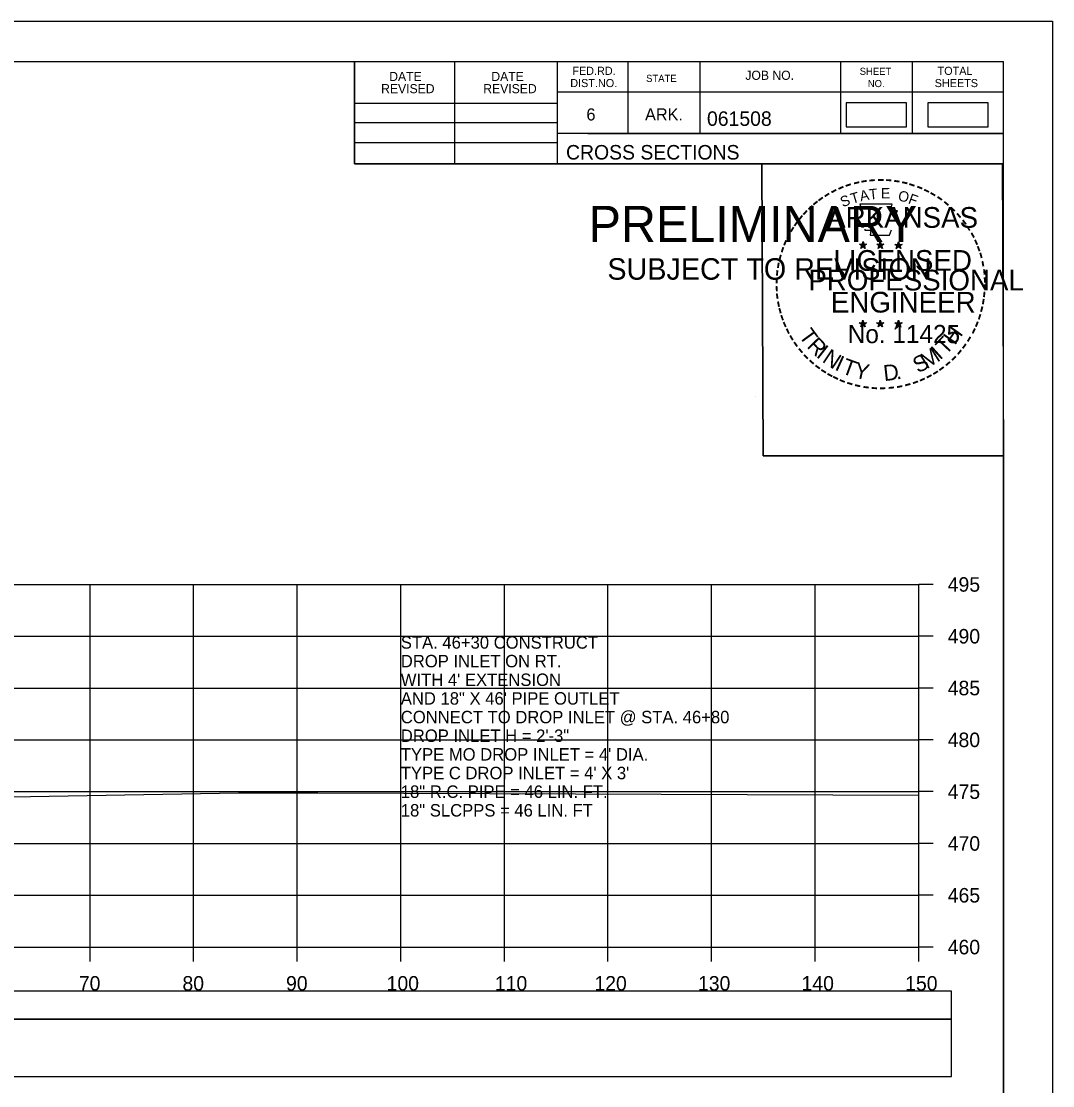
# Model space of a CAD drawing. Extents: x 1371057 to 1372761, y 380005 to 390517.
# Drawn here: x 1371624.2 to 1371723.8, y 382462.4 to 382565.1 of the extents above; entities that cross this region are included whole.
import ezdxf

# ---------------------------------------------------------------- set-up
doc = ezdxf.new("R2010")
doc.units = 0
for name, color, linetype in [('R_Axis', 7, 'Continuous'), ('R_Axis Annot', 7, 'Continuous'), ('R_Border', 7, 'Continuous'), ('R_Border PE', 7, 'Continuous'), ('R_Border Prem', 7, 'Continuous'), ('R_Detour', 7, 'Continuous'), ('R_Dimension', 7, 'Continuous'), ('R_Exist Surface', 7, 'Continuous'), ('R_Grid', 7, 'Continuous'), ('R_No Plot', 7, 'Continuous'), ('R_Water Annot', 7, 'Continuous')]:
    doc.layers.add(name, color=color, linetype=linetype)

msp = doc.modelspace()

# ---------------------------------------------------------------- linework, layer by layer
at = {"layer": 'R_Axis'}
for p, q in [((1371710.87, 382475.78), (1371710.87, 382510.78)), ((1371712.27, 382510.78), (1371710.87, 382510.78)), ((1371712.27, 382505.78), (1371710.87, 382505.78)), ((1371712.27, 382500.78), (1371710.87, 382500.78)), ((1371712.27, 382495.78), (1371710.87, 382495.78)), ((1371712.27, 382490.78), (1371710.87, 382490.78)), ((1371712.27, 382485.78), (1371710.87, 382485.78)), ((1371712.27, 382480.78), (1371710.87, 382480.78)), ((1371410.87, 382475.78), (1371710.87, 382475.78)), ((1371630.87, 382474.38), (1371630.87, 382475.78)), ((1371640.87, 382474.38), (1371640.87, 382475.78)), ((1371650.87, 382474.38), (1371650.87, 382475.78)), ((1371660.87, 382474.38), (1371660.87, 382475.78)), ((1371670.87, 382474.38), (1371670.87, 382475.78)), ((1371680.87, 382474.38), (1371680.87, 382475.78)), ((1371690.87, 382474.38), (1371690.87, 382475.78)), ((1371700.87, 382474.38), (1371700.87, 382475.78)), ((1371710.87, 382474.38), (1371710.87, 382475.78)), ((1371712.27, 382475.78), (1371710.87, 382475.78))]:
    msp.add_line(p, q, dxfattribs=at)
at = {"layer": 'R_Border'}
for p, q in [((1371402.87, 382561.24), (1371719.05, 382561.24)), ((1371656.41, 382551.36), (1371656.41, 382561.24)), ((1371666.09, 382551.36), (1371666.09, 382561.24)), ((1371675.95, 382561.24), (1371675.95, 382551.36)), ((1371682.79, 382561.24), (1371682.79, 382554.3)), ((1371689.73, 382561.24), (1371689.73, 382554.3)), ((1371703.31, 382561.24), (1371703.31, 382554.3)), ((1371710.25, 382561.24), (1371710.25, 382554.3)), ((1371719.05, 382355.78), (1371719.05, 382561.24)), ((1371719.05, 382558.3), (1371675.95, 382558.3)), ((1371719.05, 382558.32), (1371719.05, 382558.32)), ((1371656.41, 382557.22), (1371675.95, 382557.22)), ((1371656.41, 382555.36), (1371675.95, 382555.36)), ((1371719.05, 382554.3), (1371675.95, 382554.3)), ((1371678.91, 382554.3), (1371719.05, 382554.3)), ((1371656.41, 382553.42), (1371675.95, 382553.42)), ((1371719.05, 382551.36), (1371656.41, 382551.36))]:
    msp.add_line(p, q, dxfattribs=at)
at = {"layer": 'R_Border PE'}
for p, q in [((1371705.14, 382543.61), (1371705.49, 382543.5)), ((1371705.14, 382543.61), (1371705.39, 382543.57)), ((1371705.14, 382543.61), (1371705.37, 382543.49)), ((1371705.27, 382543.2), (1371705.49, 382543.5)), ((1371705.27, 382543.2), (1371705.4, 382543.45)), ((1371705.27, 382543.2), (1371705.48, 382543.42)), ((1371705.49, 382543.87), (1371705.45, 382543.61)), ((1371705.7, 382543.2), (1371705.48, 382543.42)), ((1371705.49, 382543.5), (1371705.49, 382543.87)), ((1371705.49, 382543.87), (1371705.54, 382543.62)), ((1371705.83, 382543.61), (1371705.49, 382543.5)), ((1371705.7, 382543.2), (1371705.49, 382543.5)), ((1371705.83, 382543.61), (1371705.55, 382543.56)), ((1371705.7, 382543.2), (1371705.56, 382543.5)), ((1371705.83, 382543.61), (1371705.63, 382543.51)), ((1371706.81, 382543.61), (1371707.16, 382543.5)), ((1371706.81, 382543.61), (1371707.06, 382543.57)), ((1371706.81, 382543.61), (1371707.04, 382543.49)), ((1371706.94, 382543.2), (1371707.16, 382543.5)), ((1371706.94, 382543.2), (1371707.07, 382543.45)), ((1371706.94, 382543.2), (1371707.15, 382543.42)), ((1371707.16, 382543.87), (1371707.12, 382543.61)), ((1371707.37, 382543.2), (1371707.15, 382543.42)), ((1371707.16, 382543.5), (1371707.16, 382543.87)), ((1371707.16, 382543.87), (1371707.21, 382543.62)), ((1371707.5, 382543.61), (1371707.16, 382543.5)), ((1371707.37, 382543.2), (1371707.16, 382543.5)), ((1371707.5, 382543.61), (1371707.22, 382543.56)), ((1371707.37, 382543.2), (1371707.23, 382543.5)), ((1371707.5, 382543.61), (1371707.3, 382543.51)), ((1371708.57, 382543.6), (1371708.92, 382543.49)), ((1371708.57, 382543.6), (1371708.82, 382543.56)), ((1371708.57, 382543.6), (1371708.81, 382543.48)), ((1371708.7, 382543.19), (1371708.92, 382543.49)), ((1371708.7, 382543.19), (1371708.83, 382543.44)), ((1371708.7, 382543.19), (1371708.92, 382543.41)), ((1371708.92, 382543.85), (1371708.88, 382543.6)), ((1371708.92, 382543.49), (1371708.92, 382543.85)), ((1371708.92, 382543.85), (1371708.97, 382543.6)), ((1371709.27, 382543.6), (1371708.92, 382543.49)), ((1371709.13, 382543.19), (1371708.92, 382543.49)), ((1371709.13, 382543.19), (1371708.92, 382543.41)), ((1371709.27, 382543.6), (1371708.98, 382543.55)), ((1371709.13, 382543.19), (1371709, 382543.48)), ((1371709.27, 382543.6), (1371709.06, 382543.5)), ((1371705.48, 382536.29), (1371705.44, 382536.04)), ((1371705.48, 382535.93), (1371705.48, 382536.29)), ((1371705.48, 382536.29), (1371705.53, 382536.04)), ((1371707.15, 382536.29), (1371707.11, 382536.04)), ((1371707.15, 382535.93), (1371707.15, 382536.29)), ((1371707.15, 382536.29), (1371707.2, 382536.04)), ((1371708.92, 382536.28), (1371708.88, 382536.03)), ((1371708.92, 382535.92), (1371708.92, 382536.28)), ((1371708.92, 382536.28), (1371708.97, 382536.03)), ((1371705.13, 382536.04), (1371705.48, 382535.93)), ((1371705.13, 382536.04), (1371705.39, 382535.99)), ((1371705.13, 382536.04), (1371705.37, 382535.92)), ((1371705.27, 382535.63), (1371705.48, 382535.93)), ((1371705.27, 382535.63), (1371705.39, 382535.88)), ((1371705.27, 382535.63), (1371705.48, 382535.85)), ((1371705.83, 382536.04), (1371705.48, 382535.93)), ((1371705.7, 382535.63), (1371705.48, 382535.93)), ((1371705.7, 382535.63), (1371705.48, 382535.85)), ((1371705.83, 382536.04), (1371705.54, 382535.99)), ((1371705.7, 382535.63), (1371705.56, 382535.92)), ((1371705.83, 382536.04), (1371705.63, 382535.94)), ((1371706.8, 382536.04), (1371707.15, 382535.93)), ((1371706.8, 382536.04), (1371707.06, 382535.99)), ((1371706.8, 382536.04), (1371707.04, 382535.92)), ((1371706.94, 382535.63), (1371707.15, 382535.93)), ((1371706.94, 382535.63), (1371707.06, 382535.88)), ((1371706.94, 382535.63), (1371707.15, 382535.85)), ((1371707.5, 382536.04), (1371707.15, 382535.93)), ((1371707.36, 382535.63), (1371707.15, 382535.93)), ((1371707.36, 382535.63), (1371707.15, 382535.85)), ((1371707.5, 382536.04), (1371707.21, 382535.99)), ((1371707.36, 382535.63), (1371707.23, 382535.92)), ((1371707.5, 382536.04), (1371707.29, 382535.94)), ((1371708.57, 382536.03), (1371708.92, 382535.92)), ((1371708.57, 382536.03), (1371708.82, 382535.98)), ((1371708.57, 382536.03), (1371708.81, 382535.91)), ((1371708.7, 382535.62), (1371708.92, 382535.92)), ((1371708.7, 382535.62), (1371708.83, 382535.87)), ((1371708.7, 382535.62), (1371708.92, 382535.84)), ((1371709.27, 382536.03), (1371708.92, 382535.92)), ((1371709.13, 382535.62), (1371708.92, 382535.92)), ((1371709.13, 382535.62), (1371708.92, 382535.84)), ((1371709.27, 382536.03), (1371708.98, 382535.98)), ((1371709.13, 382535.62), (1371708.99, 382535.91)), ((1371709.27, 382536.03), (1371709.06, 382535.93))]:
    msp.add_line(p, q, dxfattribs=at)
for points in [[(1371705.18, 382547.49), (1371705.45, 382546.66)], [(1371708.69, 382546.57), (1371708.83, 382546.85), (1371708.15, 382546.83), (1371708.29, 382547.49), (1371705.18, 382547.49)], [(1371705.67, 382545.07), (1371705.67, 382544.98), (1371706.23, 382544.96), (1371706.18, 382544.49), (1371708.05, 382544.49), (1371708.25, 382545.02)], [(1371705.49, 382543.87), (1371705.7, 382543.2), (1371705.14, 382543.61), (1371705.83, 382543.61), (1371705.27, 382543.2), (1371705.49, 382543.87)], [(1371707.16, 382543.87), (1371707.37, 382543.2), (1371706.81, 382543.61), (1371707.5, 382543.61), (1371706.94, 382543.2), (1371707.16, 382543.87)], [(1371708.92, 382543.85), (1371709.13, 382543.19), (1371708.57, 382543.6), (1371709.27, 382543.6), (1371708.7, 382543.19), (1371708.92, 382543.85)], [(1371705.48, 382536.29), (1371705.7, 382535.63), (1371705.13, 382536.04), (1371705.83, 382536.04), (1371705.27, 382535.63), (1371705.48, 382536.29)], [(1371707.15, 382536.29), (1371707.36, 382535.63), (1371706.8, 382536.04), (1371707.5, 382536.04), (1371706.94, 382535.63), (1371707.15, 382536.29)], [(1371708.92, 382536.28), (1371709.13, 382535.62), (1371708.57, 382536.03), (1371709.27, 382536.03), (1371708.7, 382535.62), (1371708.92, 382536.28)]]:
    msp.add_lwpolyline(points, dxfattribs=at)
for centre, radius in [((1371705.49, 382543.5), 0.172), ((1371705.49, 382543.5), 0.145), ((1371705.49, 382543.5), 0.116), ((1371705.49, 382543.5), 0.0991), ((1371705.49, 382543.5), 0.0747), ((1371705.49, 382543.5), 0.0495), ((1371705.49, 382543.5), 0.0296), ((1371707.16, 382543.5), 0.172), ((1371707.16, 382543.5), 0.145), ((1371707.16, 382543.5), 0.116), ((1371707.16, 382543.5), 0.0991), ((1371707.16, 382543.5), 0.0747), ((1371707.16, 382543.5), 0.0495), ((1371707.16, 382543.5), 0.0296), ((1371708.92, 382543.49), 0.172), ((1371708.92, 382543.49), 0.145), ((1371708.92, 382543.49), 0.116), ((1371708.92, 382543.49), 0.0991), ((1371708.92, 382543.49), 0.0747), ((1371708.92, 382543.49), 0.0495), ((1371708.92, 382543.49), 0.0296), ((1371705.48, 382535.93), 0.172), ((1371705.48, 382535.93), 0.145), ((1371705.48, 382535.93), 0.116), ((1371705.48, 382535.93), 0.0991), ((1371705.48, 382535.93), 0.0747), ((1371705.48, 382535.93), 0.0495), ((1371705.48, 382535.93), 0.0296), ((1371707.15, 382535.93), 0.172), ((1371707.15, 382535.93), 0.145), ((1371707.15, 382535.93), 0.116), ((1371707.15, 382535.93), 0.0991), ((1371707.15, 382535.93), 0.0747), ((1371707.15, 382535.93), 0.0495), ((1371707.15, 382535.93), 0.0296), ((1371708.92, 382535.92), 0.172), ((1371708.92, 382535.92), 0.145), ((1371708.92, 382535.92), 0.116), ((1371708.92, 382535.92), 0.0991), ((1371708.92, 382535.92), 0.0747), ((1371708.92, 382535.92), 0.0495), ((1371708.92, 382535.92), 0.0296)]:
    msp.add_circle(centre, radius, dxfattribs=at)
at = {"layer": 'R_Detour'}
msp.add_lwpolyline([(1371407.72, 382468.82), (1371714.03, 382468.82), (1371714.03, 382471.53), (1371407.72, 382471.53)], close=True, dxfattribs=at)
at = {"layer": 'R_Dimension'}
for points in [[(1371703.87, 382554.95), (1371709.7, 382554.95), (1371709.7, 382557.26), (1371703.87, 382557.26)], [(1371711.74, 382554.95), (1371717.57, 382554.95), (1371717.57, 382557.26), (1371711.74, 382557.26)], [(1371407.72, 382463.3), (1371714.03, 382463.3), (1371714.03, 382468.82), (1371407.72, 382468.82)]]:
    msp.add_lwpolyline(points, close=True, dxfattribs=at)
at = {"layer": 'R_Exist Surface'}
msp.add_lwpolyline([(1371621.42, 382490.24), (1371645.2, 382490.68), (1371646.29, 382490.68), (1371652.85, 382490.66), (1371710.87, 382490.44)], dxfattribs=at)
at = {"layer": 'R_Grid'}
for p, q in [((1371410.87, 382510.78), (1371710.87, 382510.78)), ((1371630.87, 382475.78), (1371630.87, 382510.78)), ((1371640.87, 382475.78), (1371640.87, 382510.78)), ((1371650.87, 382475.78), (1371650.87, 382510.78)), ((1371660.87, 382475.78), (1371660.87, 382510.78)), ((1371670.87, 382475.78), (1371670.87, 382510.78)), ((1371680.87, 382475.78), (1371680.87, 382510.78)), ((1371690.87, 382475.78), (1371690.87, 382510.78)), ((1371700.87, 382475.78), (1371700.87, 382510.78)), ((1371710.87, 382475.78), (1371710.87, 382510.78)), ((1371410.87, 382505.78), (1371710.87, 382505.78)), ((1371410.87, 382500.78), (1371710.87, 382500.78)), ((1371410.87, 382495.78), (1371710.87, 382495.78)), ((1371410.87, 382490.78), (1371710.87, 382490.78)), ((1371410.87, 382485.78), (1371710.87, 382485.78)), ((1371410.87, 382480.78), (1371710.87, 382480.78)), ((1371410.87, 382475.78), (1371710.87, 382475.78))]:
    msp.add_line(p, q, dxfattribs=at)
at = {"layer": 'R_No Plot'}
for p, q in [((1371390.47, 382565.13), (1371723.8, 382565.13)), ((1371695.09, 382528.9), (1371695.09, 382528.9))]:
    msp.add_line(p, q, dxfattribs=at)
for points in [[(1371390.46, 382565.13), (1371723.8, 382565.13), (1371723.8, 382351.79), (1371390.46, 382351.79)], [(1371636.79, 382561.24), (1371656.41, 382561.24), (1371656.41, 382551.36), (1371672.52, 382551.36), (1371695.72, 382551.36), (1371695.84, 382523.2), (1371719.05, 382523.2), (1371719.05, 382355.78), (1371402.87, 382355.78), (1371402.87, 382561.24)], [(1371695.72, 382551.36), (1371718.93, 382551.36), (1371719.05, 382523.2), (1371695.84, 382523.2)]]:
    msp.add_lwpolyline(points, close=True, dxfattribs=at)

# ---------------------------------------------------------------- texts
at = {"layer": 'R_Axis Annot'}
for s, p in [('495', (1371713.67, 382510.08)), ('490', (1371713.67, 382505.08)), ('485', (1371713.67, 382500.08)), ('480', (1371713.67, 382495.08)), ('475', (1371713.67, 382490.08)), ('470', (1371713.67, 382485.08)), ('465', (1371713.67, 382480.08)), ('460', (1371713.67, 382475.08)), ('70', (1371629.79, 382471.58)), ('80', (1371639.79, 382471.58)), ('90', (1371649.79, 382471.58)), ('100', (1371659.5, 382471.58)), ('110', (1371669.95, 382471.58)), ('120', (1371679.56, 382471.58)), ('130', (1371689.56, 382471.58)), ('140', (1371699.56, 382471.58)), ('150', (1371709.56, 382471.58))]:
    msp.add_text(s, height=1.4, dxfattribs=at).set_placement(p)
at = {"layer": 'R_Border'}
for s, height, p in [('DATE', 0.879, (1371659.75, 382559.37)), ('DATE', 0.879, (1371669.61, 382559.37)), ('FED.RD.', 0.782, (1371677.43, 382559.96)), ('STATE', 0.684, (1371684.55, 382559.28)), ('JOB NO.', 0.879, (1371694.13, 382559.48)), ('SHEET', 0.684, (1371705.17, 382559.96)), ('TOTAL', 0.782, (1371712.69, 382559.96)), ('REVISED', 0.879, (1371658.97, 382558.19)), ('REVISED', 0.879, (1371668.83, 382558.19)), ('DIST.NO.', 0.782, (1371677.23, 382558.78)), ('NO.', 0.684, (1371705.95, 382558.78)), ('SHEETS', 0.782, (1371712.41, 382558.78)), ('6', 1.17, (1371678.79, 382555.56)), ('ARK.', 1.172, (1371684.45, 382555.56)), ('061508', 1.4, (1371690.43, 382555.04)), ('CROSS SECTIONS', 1.4, (1371676.82, 382551.79))]:
    msp.add_text(s, height=height, rotation=360, dxfattribs=at).set_placement(p)
at = {"layer": 'R_Border PE'}
for s, height, rotation, p in [('-', 1.6, 13.6301, (1371704.68, 382548.86)), ('-', 1.6, 10.2193, (1371705.35, 382549.02)), ('-', 1.6, 5.8968, (1371706.08, 382549.13)), ('-', 1.6, 0.1862, (1371706.86, 382549.2)), ('-', 1.6, 357.743, (1371707.58, 382549.19)), ('-', 1.6, 352.1617, (1371708.32, 382549.13)), ('-', 1.6, 347.2049, (1371709.04, 382549.02)), ('-', 1.6, 34.0636, (1371702.06, 382547.66)), ('-', 1.6, 28.7918, (1371702.66, 382548.03)), ('-', 1.6, 24.3072, (1371703.29, 382548.35)), ('-', 1.6, 19.1761, (1371703.93, 382548.62)), ('T', 1, 16.4036, (1371704.45, 382547.5)), ('A', 1, 11.2132, (1371705.27, 382547.75)), ('T', 1, 6.0228, (1371706.12, 382547.92)), ('E', 1, 0.8323, (1371707.23, 382548.03)), ('O', 1, 350.4515, (1371708.83, 382547.82)), ('-', 1.6, 342.3362, (1371709.68, 382548.86)), ('-', 1.6, 337.8551, (1371710.41, 382548.64)), ('-', 1.6, 334.1211, (1371711.04, 382548.37)), ('-', 1.6, 329.6409, (1371711.62, 382548.09)), ('-', 1.6, 38.9507, (1371701.01, 382546.89)), ('-', 1.6, 36.2317, (1371701.48, 382547.27)), ('S', 1, 21.594, (1371703.53, 382547.17)), ('F', 1, 340.0707, (1371709.79, 382547.59)), ('-', 1.6, 325.8627, (1371712.26, 382547.73)), ('-', 1.6, 320.5297, (1371712.87, 382547.3)), ('-', 1.6, 48.423, (1371700.13, 382545.99)), ('-', 1.6, 42.9622, (1371700.58, 382546.47)), ('ARKANSAS', 2, 360, (1371702.03, 382545.2)), ('-', 1.6, 315.5786, (1371713.47, 382546.81)), ('-', 1.6, 309.8797, (1371714.04, 382546.26)), ('-', 1.6, 54.2325, (1371699.31, 382544.94)), ('-', 1.6, 50.6142, (1371699.72, 382545.51)), ('-', 1.6, 306.6522, (1371714.57, 382545.66)), ('-', 1.6, 62.8713, (1371698.67, 382543.8)), ('-', 1.6, 58.0706, (1371698.99, 382544.41)), ('-', 1.4, 303.6753, (1371715.05, 382545.09)), ('-', 1.6, 299.6684, (1371715.37, 382544.49)), ('-', 1.6, 67.7743, (1371698.41, 382543.19)), ('DWB', 0.01, 360, (1371705.47, 382543.5)), ('DWB', 0.01, 360, (1371707.14, 382543.5)), ('DWB', 0.01, 360, (1371708.91, 382543.49)), ('-', 1.6, 294.6628, (1371715.7, 382543.87)), ('-', 1.6, 290.5728, (1371715.95, 382543.3)), ('-', 1.6, 75.461, (1371698, 382541.84)), ('-', 1.6, 72.3945, (1371698.2, 382542.56)), ('LICENSED', 2, 360, (1371702.63, 382541.05)), ('-', 1.6, 285.1233, (1371716.19, 382542.72)), ('-', 1.6, 81.2013, (1371697.87, 382541.13)), ('-', 1.6, 280.5493, (1371716.39, 382541.97)), ('-', 1.6, 89.0622, (1371697.77, 382539.74)), ('-', 1.6, 85.1863, (1371697.79, 382540.44)), ('PROFESSIONAL', 2, 360, (1371700.21, 382539.15)), ('-', 1.6, 276.5962, (1371716.55, 382541.21)), ('-', 1.6, 274.3301, (1371716.61, 382540.48)), ('-', 1.6, 94.1959, (1371697.8, 382539.01)), ('-', 1.6, 269.9407, (1371716.64, 382539.85)), ('-', 1.6, 98.9479, (1371697.87, 382538.35)), ('ENGINEER', 2, 360, (1371702.39, 382537.02)), ('-', 1.6, 260.9953, (1371716.55, 382538.53)), ('-', 1.6, 263.5172, (1371716.62, 382539.19)), ('-', 1.6, 101.7149, (1371698.01, 382537.61)), ('-', 1.6, 105.4578, (1371698.17, 382537.02)), ('-', 1.6, 255.7626, (1371716.44, 382537.85)), ('-', 1.6, 109.0874, (1371698.38, 382536.39)), ('-', 1.6, 247.8887, (1371716.04, 382536.46)), ('-', 1.6, 252.8681, (1371716.26, 382537.13)), ('-', 1.6, 114.0643, (1371698.64, 382535.79)), ('-', 1.6, 115.7289, (1371698.94, 382535.17)), ('T', 1.54, 306.0406, (1371699.24, 382534.77)), ('No. 11425', 1.757, 360, (1371704.02, 382534.07)), ('DWB', 0.01, 360, (1371705.47, 382535.92)), ('DWB', 0.01, 360, (1371707.14, 382535.92)), ('DWB', 0.01, 360, (1371708.91, 382535.91)), ('H', 1.54, 54.6088, (1371714.36, 382533.8)), ('-', 1.6, 244.6197, (1371715.78, 382535.83)), ('-', 1.6, 120.4471, (1371699.3, 382534.59)), ('-', 1.6, 125.8934, (1371699.7, 382534.03)), ('R', 1.54, 314.005, (1371700, 382533.72)), ('T', 1.54, 46.6444, (1371713.47, 382532.86)), ('-', 1.6, 239.0712, (1371715.38, 382535.08)), ('-', 1.6, 130.7181, (1371700.17, 382533.48)), ('I', 1.54, 321.9694, (1371700.9, 382532.79)), ('N', 1.54, 326.5002, (1371701.47, 382532.31)), ('M', 1.54, 32.6563, (1371711.63, 382531.53)), ('I', 1.54, 42.1136, (1371712.91, 382532.38)), ('-', 1.6, 231.2538, (1371714.55, 382533.86)), ('-', 1.6, 233.8452, (1371714.98, 382534.43)), ('-', 1.6, 134.2238, (1371700.68, 382532.93)), ('-', 1.6, 138.9338, (1371701.21, 382532.47)), ('I', 1.54, 335.3603, (1371702.68, 382531.53)), ('T', 1.54, 339.8912, (1371703.34, 382531.2)), ('Y', 1.54, 347.8556, (1371704.56, 382530.76)), ('S', 1.54, 26.9312, (1371710.79, 382531.13)), ('-', 1.6, 221.0851, (1371713.55, 382532.79)), ('-', 1.6, 225.7653, (1371714.07, 382533.3)), ('-', 1.6, 144.6463, (1371701.76, 382532.06)), ('-', 1.6, 148.0898, (1371702.32, 382531.69)), ('-', 1.6, 151.5704, (1371702.9, 382531.36)), ('D', 1.54, 6.3969, (1371707.54, 382530.4)), ('-', 1.6, 207.3568, (1371711.91, 382531.58)), ('-', 1.6, 212.2491, (1371712.47, 382531.93)), ('-', 1.6, 215.7363, (1371713, 382532.32)), ('-', 1.6, 154.6002, (1371703.43, 382531.12)), ('-', 1.6, 158.5612, (1371704.05, 382530.86)), ('-', 1.6, 162.7983, (1371704.74, 382530.65)), ('-', 1.6, 167.5555, (1371705.45, 382530.49)), ('-', 1.6, 191.2858, (1371709.26, 382530.55)), ('.', 1.54, 13.7642, (1371708.74, 382530.53)), ('-', 1.6, 195.4743, (1371709.99, 382530.75)), ('-', 1.6, 200.7184, (1371710.67, 382530.99)), ('-', 1.6, 204.2516, (1371711.29, 382531.26)), ('-', 1.6, 173.1155, (1371706.22, 382530.38)), ('-', 1.6, 176.5183, (1371706.97, 382530.32)), ('-', 1.6, 181.5918, (1371707.72, 382530.34)), ('-', 1.6, 185.8167, (1371708.52, 382530.42))]:
    msp.add_text(s, height=height, rotation=rotation, dxfattribs=at).set_placement(p)
at = {"layer": 'R_Border Prem'}
for s, height, p in [('PRELIMINARY', 3.5, (1371679, 382543.82)), ('DWB', 0.01, (1371679.75, 382545.67)), ('SUBJECT TO REVISION', 2.0751, (1371680.81, 382540.19))]:
    msp.add_text(s, height=height, rotation=360, dxfattribs=at).set_placement(p)
at = {"layer": 'R_Water Annot'}
for s, p in [('STA. 46+30 CONSTRUCT', (1371660.87, 382504.58)), ('DROP INLET ON RT.', (1371660.87, 382502.78)), ("WITH 4' EXTENSION", (1371660.87, 382500.98)), ('AND 18" X 46\' PIPE OUTLET', (1371660.87, 382499.18)), ('CONNECT TO DROP INLET @ STA. 46+80', (1371660.87, 382497.38)), ('DROP INLET H = 2\'-3"', (1371660.87, 382495.58)), ("TYPE MO DROP INLET = 4' DIA.", (1371660.87, 382493.78)), ("TYPE C DROP INLET = 4' X 3'", (1371660.87, 382491.98)), ('18" R.C. PIPE = 46 LIN. FT.', (1371660.87, 382490.18)), ('18" SLCPPS = 46 LIN. FT', (1371660.87, 382488.38))]:
    msp.add_text(s, height=1.2, dxfattribs=at).set_placement(p)

doc.saveas('drawing.dxf')
